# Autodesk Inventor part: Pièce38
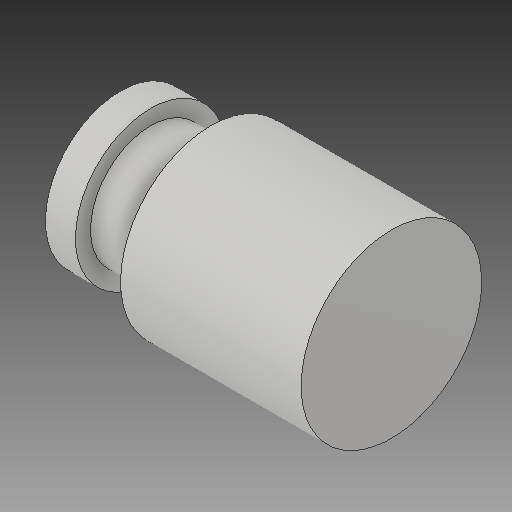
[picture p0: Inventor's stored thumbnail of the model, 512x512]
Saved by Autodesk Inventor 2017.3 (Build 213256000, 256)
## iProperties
Created: 2007-12
Part Number: Pièce38
Material: Générique
Document SubType Name: Modeling
Designer: ficho
Density: 1 g/cm^3
Appearance: Par défaut
Author: ficho
Sending System: SolidWorks 2009
Last Author: christophe
Last Saved: 2011-02-10
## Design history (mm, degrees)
feature "Révolution1"
node "Solide1"
